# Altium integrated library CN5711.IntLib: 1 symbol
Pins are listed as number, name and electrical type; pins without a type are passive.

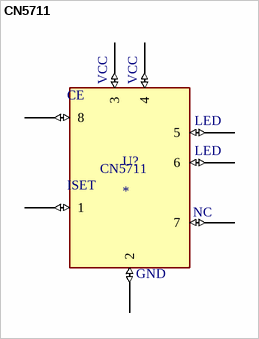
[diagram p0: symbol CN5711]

## CN5711
designator U?
Box Metal, Aluminum Natural Cover Included 8.752 L x 5.744 W (222.30mm x 145.90mm) X 2.254 (57.25mm); MP: CN5711; MF: BUD Industries
footprint SOIC-8-G
pins: 1 (io), 2 (io), 3 (io), 4 (io), 5 (io), 6 (io), 7 (io), 8 (io)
